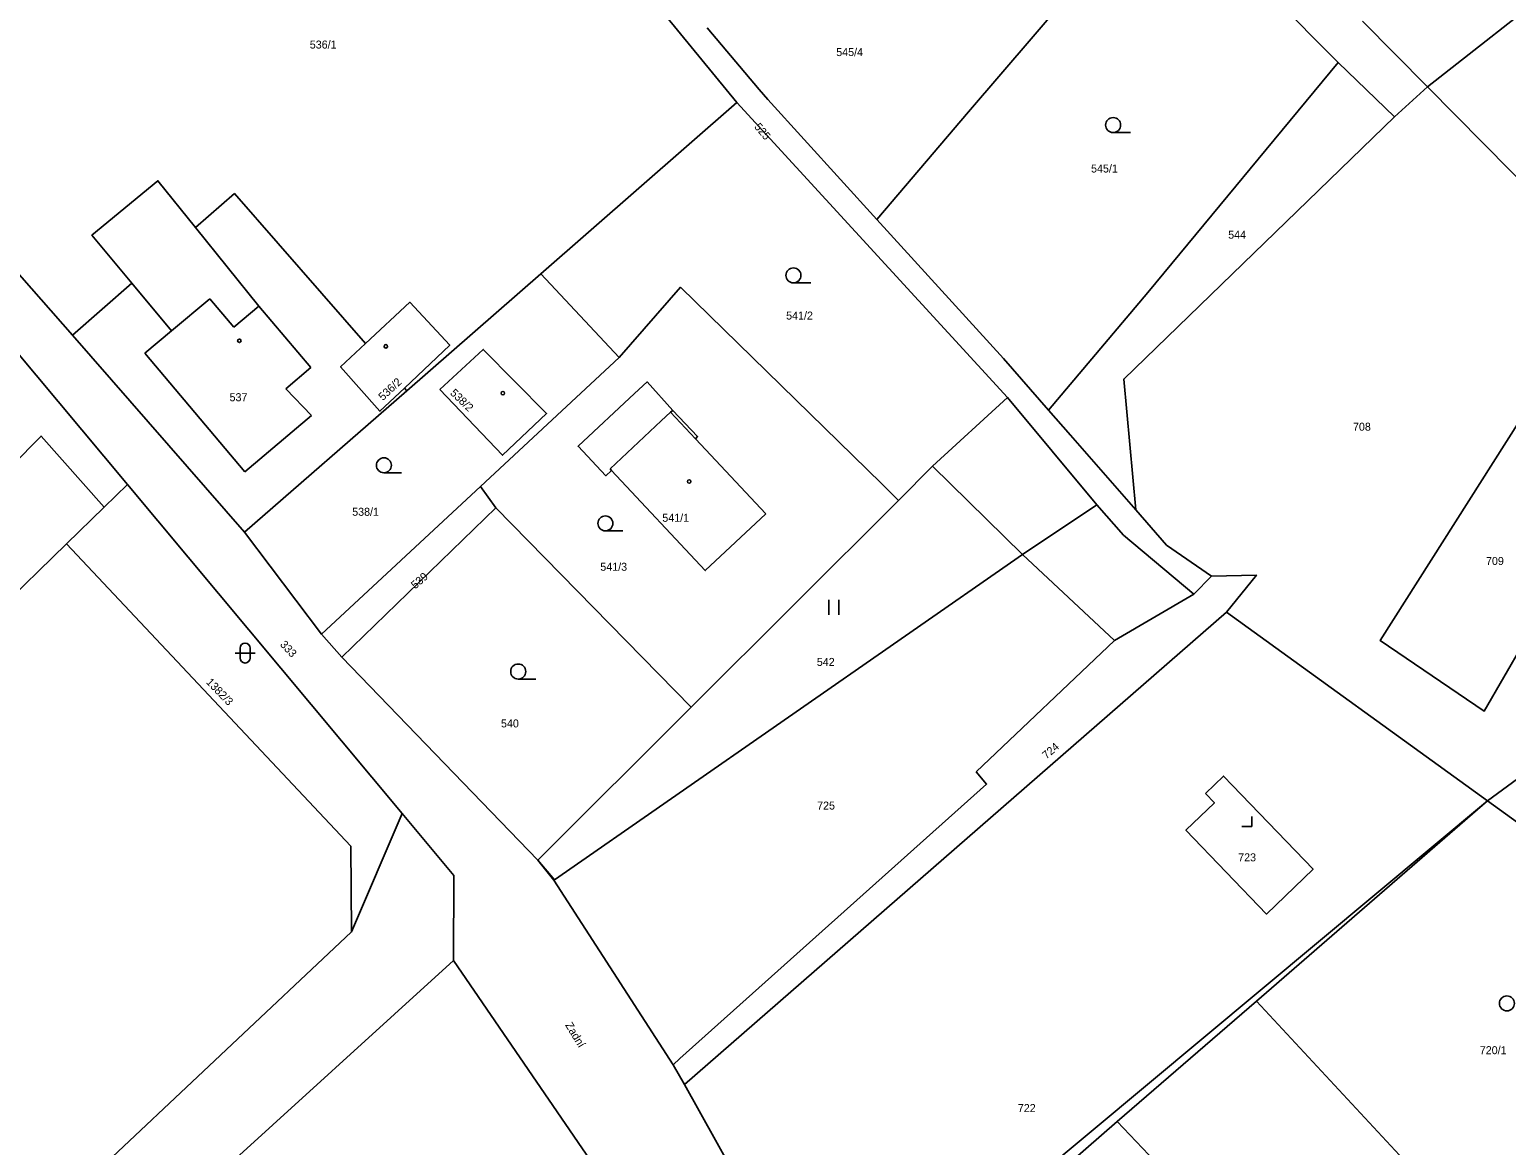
# Model space of a CAD drawing. Extents: x -719706 to -718922, y -950351 to -949651.
# Drawn here: x -719485 to -719337.3, y -949856.8 to -949745.2 of the extents above; entities that cross this region are included whole.
import ezdxf

# ---------------------------------------------------------------- set-up
doc = ezdxf.new("R2010")
doc.units = 0
doc.layers.add('Doplňující texty', color=7, linetype='Continuous')

msp = doc.modelspace()

# ---------------------------------------------------------------- linework, layer by layer
at = {"layer": 'Doplňující texty'}
for p, q in [((-719354.14, -949748.46), (-719371.7, -949730.77)), ((-719345.2, -949750.91), (-719351.71, -949744.34)), ((-719348.52, -949753.91), (-719354.14, -949748.46)), ((-719348.52, -949753.91), (-719345.2, -949750.91)), ((-719433.88, -949769.6), (-719414.27, -949752.48)), ((-719414.27, -949752.48), (-719387.19, -949781.98)), ((-719376.64, -949755.47), (-719374.89, -949755.47)), ((-719468.39, -949764.98), (-719462.06, -949772.84)), ((-719474.76, -949770.55), (-719470.79, -949775.3)), ((-719447.28, -949781.3), (-719433.88, -949769.6)), ((-719426.02, -949777.98), (-719433.88, -949769.6)), ((-719408.61, -949770.51), (-719406.86, -949770.51)), ((-719466.98, -949772.09), (-719470.79, -949775.3)), ((-719466.98, -949772.09), (-719464.57, -949774.95)), ((-719464.57, -949774.95), (-719462.06, -949772.84)), ((-719462.06, -949772.84), (-719456.87, -949778.99)), ((-719463.49, -949795.45), (-719480.71, -949775.75)), ((-719470.79, -949775.3), (-719473.45, -949777.54)), ((-719463.45, -949789.41), (-719473.45, -949777.54)), ((-719439.91, -949790.89), (-719426.02, -949777.98)), ((-719456.87, -949778.99), (-719459.38, -949781.11)), ((-719463.49, -949795.45), (-719447.28, -949781.3)), ((-719459.38, -949781.11), (-719456.81, -949783.79)), ((-719447.51, -949781.04), (-719447.28, -949781.3)), ((-719387.19, -949781.98), (-719378.26, -949792.72)), ((-719456.81, -949783.79), (-719463.45, -949789.41)), ((-719421.83, -949784.32), (-719420.9, -949783.44)), ((-719420.9, -949783.44), (-719420.68, -949783.27)), ((-719418.41, -949786.1), (-719420.9, -949783.44)), ((-719426.95, -949789.12), (-719421.83, -949784.32)), ((-719449.56, -949789.51), (-719447.81, -949789.51)), ((-719426.81, -949789.27), (-719426.95, -949789.12)), ((-719394.72, -949788.83), (-719385.72, -949797.68)), ((-719475.21, -949790.69), (-719477.53, -949792.94)), ((-719475.21, -949790.69), (-719447.72, -949823.6)), ((-719455.79, -949805.66), (-719439.91, -949790.89)), ((-719438.36, -949793), (-719439.91, -949790.89)), ((-719418.83, -949812.95), (-719398.12, -949792.29)), ((-719481.29, -949796.6), (-719477.53, -949792.94)), ((-719453.76, -949807.97), (-719438.36, -949793)), ((-719418.83, -949812.95), (-719438.36, -949793)), ((-719455.79, -949805.66), (-719463.49, -949795.45)), ((-719427.41, -949795.32), (-719425.66, -949795.32)), ((-719481.29, -949796.6), (-719529.7, -949843.78)), ((-719385.72, -949797.68), (-719376.51, -949806.3)), ((-719366.82, -949799.86), (-719368.56, -949801.65)), ((-719405.07, -949803.72), (-719405.07, -949802.22)), ((-719404.07, -949803.72), (-719404.07, -949802.22)), ((-719365.31, -949803.46), (-719419.49, -949850.7)), ((-719365.31, -949803.46), (-719339.21, -949822.33)), ((-719453.76, -949807.97), (-719455.79, -949805.66)), ((-719464.44, -949807.54), (-719462.44, -949807.54)), ((-719463.94, -949807.04), (-719463.94, -949808.04)), ((-719462.94, -949808.04), (-719462.94, -949807.04)), ((-719434.17, -949828.27), (-719453.76, -949807.97)), ((-719436.13, -949810.14), (-719434.38, -949810.14)), ((-719434.17, -949828.27), (-719418.83, -949812.95)), ((-719339.21, -949822.33), (-719335.71, -949819.77)), ((-719447.72, -949823.6), (-719452.8, -949835.44)), ((-719339.21, -949822.33), (-719406.63, -949878.59)), ((-719339.21, -949822.33), (-719362.32, -949842.36)), ((-719363.76, -949824.89), (-719362.76, -949824.89)), ((-719362.76, -949824.89), (-719362.76, -949823.89)), ((-719434.17, -949828.27), (-719432.5, -949830.23)), ((-719432.58, -949830.26), (-719434.17, -949828.27)), ((-719420.63, -949848.73), (-719432.58, -949830.26)), ((-719452.8, -949835.44), (-719497.78, -949877.76)), ((-719442.6, -949838.3), (-719510.6, -949900.1)), ((-719442.6, -949838.3), (-719417.75, -949874.56)), ((-719376.23, -949854.42), (-719362.32, -949842.36)), ((-719362.32, -949842.36), (-719329.12, -949878.08)), ((-719419.97, -949848.09), (-719420.63, -949848.73)), ((-719419.49, -949850.7), (-719420.63, -949848.73)), ((-719376.23, -949854.42), (-719385.52, -949862.47))]:
    msp.add_line(p, q, dxfattribs=at)
for points in [[(-719447.2, -949699.27), (-719433.89, -949728.49), (-719414.27, -949752.48)], [(-719371.7, -949730.77), (-719391.11, -949753.39), (-719400.26, -949764.16)], [(-719345.2, -949750.91), (-719331.79, -949740.33), (-719325.08, -949745.33)], [(-719400.26, -949764.16), (-719411.17, -949752.18), (-719412.04, -949751.15), (-719417.23, -949745)], [(-719325.08, -949745.33), (-719333.47, -949758.94), (-719334.03, -949762.2), (-719345.2, -949750.91)], [(-719354.14, -949748.46), (-719373.17, -949771.47), (-719383.09, -949783.24)], [(-719374.38, -949793.21), (-719375.58, -949780.14), (-719348.52, -949753.91)], [(-719480.71, -949775.75), (-719487.92, -949767.49), (-719500.34, -949755.14)], [(-719507.56, -949758.01), (-719491.3, -949771.44), (-719475.21, -949790.69)], [(-719480.71, -949775.75), (-719474.76, -949770.55), (-719478.76, -949765.74), (-719472.15, -949760.3), (-719468.39, -949764.98), (-719464.5, -949761.58), (-719451.4, -949776.58)], [(-719383.09, -949783.24), (-719387.61, -949778.06), (-719400.26, -949764.16)], [(-719426.02, -949777.98), (-719419.89, -949770.94), (-719399.78, -949790.62), (-719398.12, -949792.29)], [(-719451.4, -949776.58), (-719446.96, -949772.45), (-719442.97, -949776.74), (-719447.51, -949781.04)], [(-719451.4, -949776.58), (-719453.89, -949778.9), (-719449.95, -949783.35), (-719447.51, -949781.04)], [(-719443.95, -949781.18), (-719439.63, -949777.16), (-719433.3, -949783.59), (-719437.7, -949787.75), (-719443.95, -949781.18)], [(-719411.36, -949793.61), (-719418.41, -949786.1), (-719418.19, -949785.89), (-719420.68, -949783.27), (-719423.24, -949780.41), (-719424.49, -949781.59), (-719430.14, -949786.86), (-719427.38, -949789.8), (-719426.81, -949789.27), (-719417.42, -949799.29), (-719411.36, -949793.61)], [(-719335.61, -949806.55), (-719339.53, -949813.35), (-719349.95, -949806.28), (-719333.54, -949780.44), (-719326.66, -949787.36), (-719335.39, -949801.88), (-719333.25, -949803.47), (-719332.97, -949802.92), (-719330.02, -949805.03), (-719332.2, -949808.63), (-719335.61, -949806.55)], [(-719398.12, -949792.29), (-719394.72, -949788.83), (-719387.19, -949781.98)], [(-719374.38, -949793.21), (-719380.91, -949785.74), (-719383.09, -949783.24)], [(-719477.53, -949792.94), (-719483.83, -949785.83), (-719492.61, -949794.69), (-719493.36, -949795.33), (-719494.74, -949795.88), (-719496.7, -949796.36), (-719498.17, -949796.44), (-719499.18, -949796.27), (-719501.04, -949795.57), (-719502.36, -949794.85), (-719503.87, -949793.54), (-719504.79, -949792.38), (-719505.59, -949791.15), (-719506.95, -949803.33), (-719508, -949803.22)], [(-719432.58, -949830.26), (-719432.5, -949830.23), (-719385.72, -949797.68), (-719378.26, -949792.72)], [(-719378.26, -949792.72), (-719375.62, -949795.74), (-719368.56, -949801.65)], [(-719366.82, -949799.86), (-719371.3, -949796.74), (-719374.38, -949793.21)], [(-719452.8, -949835.44), (-719452.88, -949826.85), (-719481.29, -949796.6)], [(-719365.31, -949803.46), (-719362.32, -949799.74), (-719366.82, -949799.86)], [(-719368.56, -949801.65), (-719376.51, -949806.3), (-719390.33, -949819.43)], [(-719390.33, -949819.43), (-719389.29, -949820.65), (-719419.97, -949848.09)], [(-719367.4, -949821.58), (-719365.6, -949819.85), (-719364.7, -949820.78), (-719356.65, -949829.17), (-719361.31, -949833.65), (-719369.36, -949825.26), (-719366.51, -949822.51), (-719367.4, -949821.58)], [(-719447.72, -949823.6), (-719442.57, -949829.8), (-719442.6, -949838.3)], [(-719301.23, -949855.39), (-719303.31, -949848.28), (-719339.21, -949822.33)], [(-719406.63, -949878.59), (-719411.45, -949864.22), (-719413.3, -949861.83), (-719419.49, -949850.7)], [(-719367.2, -949882.75), (-719364.09, -949880.68), (-719368.8, -949874.17), (-719362.32, -949869.09), (-719376.23, -949854.42)]]:
    msp.add_lwpolyline(points, dxfattribs=at)
for centre, radius in [((-719376.64, -949754.72), 0.75), ((-719408.61, -949769.76), 0.75), ((-719464.01, -949776.3), 0.175), ((-719449.37, -949776.86), 0.175), ((-719437.66, -949781.54), 0.175), ((-719449.56, -949788.76), 0.75), ((-719419.03, -949790.38), 0.175), ((-719427.41, -949794.57), 0.75), ((-719436.13, -949809.39), 0.75), ((-719337.27, -949842.59), 0.75)]:
    msp.add_circle(centre, radius, dxfattribs=at)
for centre, start, end in [((-719463.44, -949807.04), 0, 180), ((-719463.44, -949808.04), 180, 359.9879)]:
    msp.add_arc(centre, 0.5, start, end, dxfattribs=at)

# ---------------------------------------------------------------- texts
for s, p in [('536/1', (-719456.97, -949747.07)), ('545/4', (-719404.33, -949747.82)), ('545/1', (-719378.85, -949759.47)), ('544', (-719365.14, -949766.09)), ('541/2', (-719409.34, -949774.18)), ('537', (-719464.99, -949782.35)), ('708', (-719352.66, -949785.3)), ('538/1', (-719452.73, -949793.81)), ('541/1', (-719421.72, -949794.41)), ('541/3', (-719427.92, -949799.31)), ('709', (-719339.36, -949798.73)), ('542', (-719406.27, -949808.83)), ('540', (-719437.85, -949814.98)), ('725', (-719406.24, -949823.2)), ('723', (-719364.14, -949828.38)), ('720/1', (-719339.98, -949847.67)), ('722', (-719386.17, -949853.46))]:
    msp.add_text(s, height=0.8, dxfattribs=at).set_placement(p)
for s, rotation, p in [('525', 310, (-719412.58, -949754.93)), ('536/2', 43, (-719449.66, -949782.34)), ('538/2', 316, (-719443, -949781.6)), ('539', 41, (-719446.42, -949801.18)), ('333', 313, (-719460, -949806.74)), ('1382/3', 314, (-719467.39, -949810.51)), ('724', 41, (-719383.31, -949818.2)), ('Zadní', 301, (-719431.46, -949844.76))]:
    msp.add_text(s, height=0.8, rotation=rotation, dxfattribs=at).set_placement(p)

doc.saveas('drawing.dxf')
